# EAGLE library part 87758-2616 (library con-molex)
26 Pin - 2mm Dual Row Single Wafer, Vertical T/H HDR Source: http://www.molex.com/pdm_docs/sd/877580616_sd.pdf
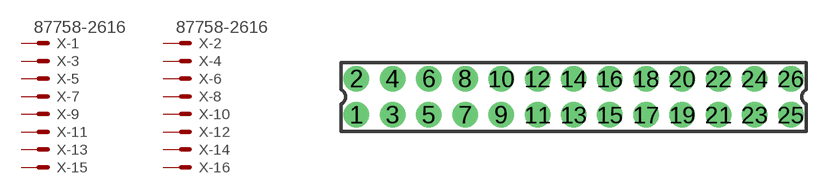
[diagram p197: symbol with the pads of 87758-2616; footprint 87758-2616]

Designator prefix X; gates -1=MV -2=MV -3=M -4=M -5=M -6=M -7=M -8=M -9=M -10=M -11=M -12=M -13=M -14=M -15=M -16=M -17=M -18=M -19=M -20=M -21=M -22=M -23=M -24=M -25=M -26=M

## 87758-2616 (MPN: 87758-2616; OC_FARNELL: unknown; OC_NEWARK: 94M1541)  [87758-2616]
1  -1:S  pas
2  -2:S  pas
3  -3:S  pas
4  -4:S  pas
5  -5:S  pas
6  -6:S  pas
7  -7:S  pas
8  -8:S  pas
9  -9:S  pas
10  -10:S  pas
11  -11:S  pas
12  -12:S  pas
13  -13:S  pas
14  -14:S  pas
15  -15:S  pas
16  -16:S  pas
17  -17:S  pas
18  -18:S  pas
19  -19:S  pas
20  -20:S  pas
21  -21:S  pas
22  -22:S  pas
23  -23:S  pas
24  -24:S  pas
25  -25:S  pas
26  -26:S  pas

## Footprint 87758-2616 (pad centres in mm)
26 Pin - 2mm Dual Row Single Wafer, Vertical T/H HDR Source: http://www.molex.com/pdm_docs/sd/877580616_sd.pdf
drill 0.9 pad 1.27 round: 1 -12,-1; 2 -12,1; 3 -10,-1; 4 -10,1; 5 -8,-1; 6 -8,1; 7 -6,-1; 8 -6,1; 9 -4,-1; 10 -4,1; 11 -2,-1; 12 -2,1; 13 0,-1; 14 0,1; 15 2,-1; 16 2,1; 17 4,-1; 18 4,1; 19 6,-1; 20 6,1; 21 8,-1; 22 8,1; 23 10,-1; 24 10,1; 25 12,-1; 26 12,1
